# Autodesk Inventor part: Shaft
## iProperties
Created: 2010-04
Part Number: Shaft
Material: Steel
Document SubType Name: Modeling
Designer: a31883
Density: 1 g/cm^3
CustomPartVersion: 1
Author: a31883
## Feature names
1. Revolution1
